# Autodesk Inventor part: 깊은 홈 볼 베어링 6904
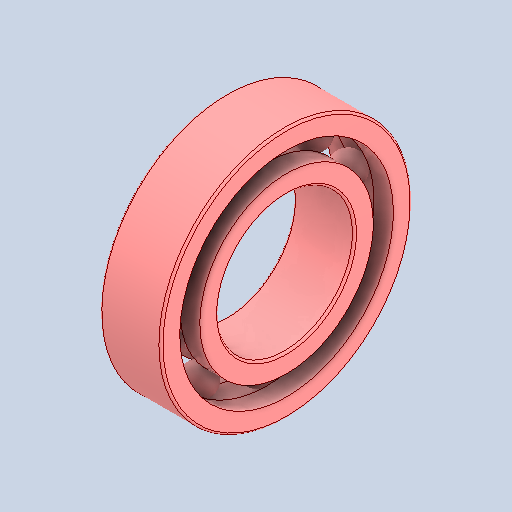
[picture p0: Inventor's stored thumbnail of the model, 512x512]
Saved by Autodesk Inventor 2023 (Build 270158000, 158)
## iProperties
Created: 2026-06
Part Number: 깊은 홈 볼 베어링 6904
Material: 강철, 연강
Description: 깊은 그루브 볼 베어링
Document SubType Name: Modeling
Designer: home
Density: 7.85 g/cm^3
Appearance: 기본값
Author: jhkim
Sending System: Autodesk Inventor 2027
Preprocessor: ST-DEVELOPER v20.1
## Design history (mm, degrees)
feature "Solid1"
feature "Solid1:1"
feature "Solid1:2"
feature "Solid1:3"
feature "Solid1:4"
feature "Solid1:5"
feature "Solid1:6"
feature "Solid1:7"
feature "Solid1:8"
feature "Solid1:9"
feature "Solid1:10"
feature "Solid1:11"
node "솔리드1"
node "솔리드2"
node "솔리드3"
node "솔리드4"
node "솔리드5"
node "솔리드6"
node "솔리드7"
node "솔리드8"
node "솔리드9"
node "솔리드10"
node "솔리드11"
node "솔리드12"
